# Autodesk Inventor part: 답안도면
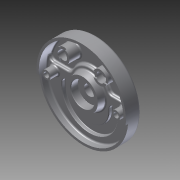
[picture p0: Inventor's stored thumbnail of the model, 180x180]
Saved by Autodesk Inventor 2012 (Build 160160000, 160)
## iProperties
Created: 2015-04
Part Number: 답안도면
Material: Default
Document SubType Name: Modeling
Designer: Owner
Mass: 399.369 g
Surface Area: 1033.6 cm^2
Volume: 399.369 cm^3
Density: 1 g/cm^3
Author: Owner
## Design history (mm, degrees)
sketch "스케치1"
  geometry: C1 r 95 at (0, 0); 1 further point
  constraints: 1 centre point, 1 coincident
  dimensions: "d0" = 190 diameter of C1
extrude "돌출1" new body sketch "스케치1" distance "d1" = 32; taper "d2" = 0 deg
sketch "스케치2"
  geometry: C1 r 95 at (0, 0) reference; C2 r 90 at (0, 0)
  constraints: 1 centre point, 1 coincident
  dimensions: "d3" = 180 diameter of C2
extrude "돌출2" cut sketch "스케치2" distance "d4" = 18; taper "d5" = 0 deg
sketch "스케치3"
  geometry: L1 (90, 14)-(-90, 14) reference; L2 (0, 0)-(0, 65.515); L3 (-35, 14)-(-32.355, 29); L4 (-32.355, 29)-(0, 29); L5 (-35, 14)-(0, 14)
  constraints: 8 end point, 3 point on line, 1 midpoint, 1 parallel, 1 perpendicular
  dimensions: "d6" = 100 deg angle of L1 L3; "d7" = 15 distance between parallel lines of L4 L1; "d8" = 70 diameter of L3.start L2
revolve "회전1" sketch "스케치3" stored, may be unused: angle "d9" = 90 deg
sketch "스케치4"
  geometry: L1 (-89.196, 12)-(-40.249, 12); L2 (40.249, 12)-(89.196, 12); C1 r 35 at (0, 0) reference; A1 r 42 centre (0, 0) between (40.249, 12) and (-40.249, 12); A2 r 90 centre (0, 0) between (89.196, 12) and (-89.196, 12); 2 further points
  constraints: 4 end point, 4 point on circle, 2 centre point, 2 coincident, 2 horizontal, 1 horizontal alignment, 1 vertical alignment, 2 other
  dimensions: "d11" = 84 diameter of A1; "d110" = 12 distance from line of C1.centre L2
extrude "돌출4" cut sketch "스케치4" distance "d15" = 7; taper "d16" = 0 deg
hole "구멍1" diameter "d19" = 23; stored, may be unused: countersink angle "d23" = 90 deg, drill point angle "d25" = 118 deg; dims "d17" = 10, "d18" = 10, "d20" = 6, "d21" = 50, "d22" = 15, "d24" = 8
sketch "스케치5"
  geometry: L1 (89.658, -7.844)-(94.638, -8.28); L2 (-89.658, -7.844)-(-94.638, -8.28); L3 (-89.658, -7.844)-(0, 0); L4 (0, 0)-(89.658, -7.844); L5 (-40.249, 12)-(-89.196, 12) reference; L6 (89.196, 12)-(40.249, 12) reference; A1 r 90 centre (0, 0) between (-89.658, -7.844) and (89.658, -7.844) reference; A2 r 95 centre (0, 0) between (94.638, -8.28) and (-94.638, -8.28) reference
  constraints: 8 end point, 4 point on circle, 2 collinear
  dimensions: "d111" = 5 deg angle of L3 L5; "d112" = 5 deg angle of L4 L6
extrude "돌출5" cut sketch "스케치5" distance "d29" = 5; taper "d30" = 0 deg
sketch "스케치6"
  geometry: L1 (-99.192, -19)-(99.192, -19); L2 (-99.192, -14)-(99.192, -14); L3 (41, -19)-(41, -14); L4 (59, -19)-(59, -14); L5 (-41, -19)-(-41, -14); L6 (-59, -19)-(-59, -14); A1 r 90 centre (0, 0) between (-89.196, 12) and (89.196, 12) reference; A2 r 9 centre (50, -14) between (59, -14) and (41, -14); A3 r 9 centre (-50, -14) between (-41, -14) and (-59, -14); A4 r 59 centre (0, -19) between (-59, -19) and (59, -19); A5 r 41 centre (0, -19) between (-41, -19) and (41, -19); 3 further points
  constraints: 12 end point, 8 point on circle, 7 point on line, 6 parallel, 5 tangent, 4 centre point, 2 coincident, 2 midpoint, 2 vertical alignment, 1 equal radius, 1 perpendicular
  dimensions: "d45" = 5 distance between parallel lines of L1 L2; "d47" = 18 distance between parallel lines of L4 L3; "d48" = 41 radius of A5; "d113" = 19 distance from line of L1 A1.centre
extrude "돌출6" cut sketch "스케치6" distance "d49" = 7; taper "d50" = 0 deg
sketch "스케치8"
  geometry: C1 r 11.5 at (0, 0) reference; C2 r 9 at (74, 0)
  constraints: 1 centre point, 1 horizontal alignment
  dimensions: "d53" = 18 diameter of C2; "d54" = 74 distance of C2.centre C1.centre
extrude "돌출7" join sketch "스케치8" stored distance "d55" = 7; taper "d56" = 0 deg
sketch "스케치9"
  geometry: C1 r 11.5 at (0, 0) reference; 1 further point
  constraints: 1 horizontal alignment
  dimensions: "d57" = 74 distance of point (74, 0) C1.centre
hole "구멍2" sketch "스케치9" at (74, 0) diameter "d58" = 11; stored, may be unused: countersink angle "d62" = 90 deg, drill point angle "d64" = 118 deg; dims "d59" = 6, "d60" = 18, "d61" = 11, "d63" = 8
sketch "스케치10"
  geometry: C1 r 11.5 at (0, 0) reference; C2 r 15 at (-40, 52)
  constraints: 1 centre point
  dimensions: "d65" = 30 diameter of C2; "d66" = 52 vertical distance of C1.centre C2.centre; "d67" = 40 horizontal distance of C1.centre C2.centre
extrude "돌출8" join sketch "스케치10" stored distance "d68" = 7; taper "d69" = 0 deg
hole "구멍3" diameter "d72" = 20; stored, may be unused: countersink angle "d76" = 90 deg, drill point angle "d78" = 118 deg; dims "d70" = 10, "d71" = 10, "d73" = 6, "d74" = 18, "d75" = 11, "d77" = 8
sketch "스케치11"
  geometry: L1 (-6, 13.748)-(-6, 8); L2 (-6, -8)-(-6, -13.748); L3 (6, 13.748)-(6, 8); L4 (6, -8)-(6, -13.748); A1 r 10 centre (0, 0) between (-6, 8) and (-6, -8) reference; A2 r 15 centre (0, 0) between (-6, 13.748) and (-6, -13.748) reference; 1 further point
  constraints: 8 end point, 8 point on circle, 6 parallel, 2 vertical
  dimensions: "d80" = 12 distance between parallel lines of L3 L1; "d81" = 12 distance between parallel lines of L4 L2
extrude "돌출9" cut sketch "스케치11" distance "d82" = 3; taper "d83" = 0 deg
sketch "스케치12"
  geometry: L1 (-13.748, 6)-(-8, 6); L2 (8, 6)-(13.748, 6); L3 (-13.748, -6)-(-8, -6); L4 (8, -6)-(13.748, -6); A1 r 10 centre (0, 0) between (-8, 6) and (8, 6) reference; A2 r 15 centre (0, 0) between (-13.748, -6) and (13.748, -6) reference; 1 further point
  constraints: 8 end point, 8 point on circle, 6 parallel, 2 horizontal
  dimensions: "d84" = 12 distance between parallel lines of L3 L1; "d85" = 12 distance between parallel lines of L4 L2
extrude "돌출10" cut sketch "스케치12" distance "d86" = 3; taper "d87" = 0 deg
sketch "스케치13"
  geometry: L1 (36.062, -36.062)-(50.912, -50.912); L2 (-36.062, -36.062)-(-50.912, -50.912); L3 (-36.062, -36.062)-(0, 0); L4 (0, 0)-(36.062, -36.062); C1 r 11.5 at (0, 0) reference; C2 r 95 at (0, 0) reference; A1 r 51 centre (0, 0) between (-36.062, -36.062) and (36.062, -36.062); A2 r 72 centre (0, 0) between (-50.912, -50.912) and (50.912, -50.912); 1 further point
  constraints: 8 end point, 5 point on circle, 3 coincident, 2 centre point, 1 collinear, 1 perpendicular, 1 vertical alignment
  dimensions: "d91" = 90 deg angle of L1 L2; "d92" = 72 radius of A2; "d93" = 51 radius of A1
extrude "돌출11" join sketch "스케치13" distance "d94" = 5; taper "d95" = 0 deg
fillet "모깎기1" dims "d98" = 5
chamfer "모따기1" distance "d101" = 1; stored, may be unused: second distance "d102" = 2, angle "d103" = 45 deg
fillet "모깎기4" dims "d104" = 3, "d122" = 5
fillet "모깎기5" dims "d105" = 5
fillet "모깎기6" dims "d106" = 1
fillet "모깎기7" dims "d114" = 10
fillet "모깎기8" dims "d115" = 3
fillet "모깎기9" dims "d116" = 3
fillet "모깎기10" dims "d117" = 3
sketch "스케치15"
  geometry: 1 further point
node "작업 평면2"
sketch "스케치16"
  geometry: 2 further points
  constraints: 1 vertical alignment, 1 other
feature "엠보싱1" sketch "스케치16" dims "d119" = 0.5, "d120" = 0
fillet "모깎기11" dims "d121" = 3
fillet "모깎기12" dims "d123" = 0.3
node "솔리드1"
mirror "대칭1"
mirror "대칭2"
other parameters: "d10" = 12, "d32" = 118, "d33" = 19, "d43" = 82, "d44" = 118, "d79" = 12, "d89" = 144, "d90" = 90 deg, "d109" = 12
